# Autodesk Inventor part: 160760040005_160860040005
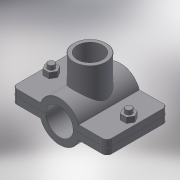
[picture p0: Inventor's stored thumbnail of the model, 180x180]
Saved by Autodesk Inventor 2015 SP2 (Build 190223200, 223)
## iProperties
Created: 2017-05
Part Number: 160760040005_160860040005
Material: Generic
Description: PLASSON SADDLE 40-1/2"
Document SubType Name: Modeling
Designer: KIM
Density: 1 g/cm^3
Appearance: Default
Author: KIM
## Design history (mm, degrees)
derived "16076.ipt"
feature "Solid1::16076.ipt"
feature "Solid2::16076.ipt"
tag "TaggingFeature1"
body "Solid1"
other parameters: "d0" = 56, "d1" = 92, "d5" = 0, "d6" = 4.6, "d7" = 92, "d8" = 0.1, "d10" = 0, "d11" = 0.4, "d14" = 24.2203, "d20" = 0.4, "d23" = 0.4, "d37" = 8, "d38" = 28, "d39" = 0, "d40" = 3, "d41" = 5, "d42" = 0, "d43" = 6, "d44" = 3, "d45" = 0, "d46" = 0.4, "d51" = 45, "d52" = 18.631, "d53" = 18, "d54" = 0, "d55" = 16, "d57" = 0, "d58" = 43.2, "d60" = 0, "d66" = 0, "B_" = 16, "G_" = 18.631, "A_" = 45, "L_" = 92, "l_2" = 18
